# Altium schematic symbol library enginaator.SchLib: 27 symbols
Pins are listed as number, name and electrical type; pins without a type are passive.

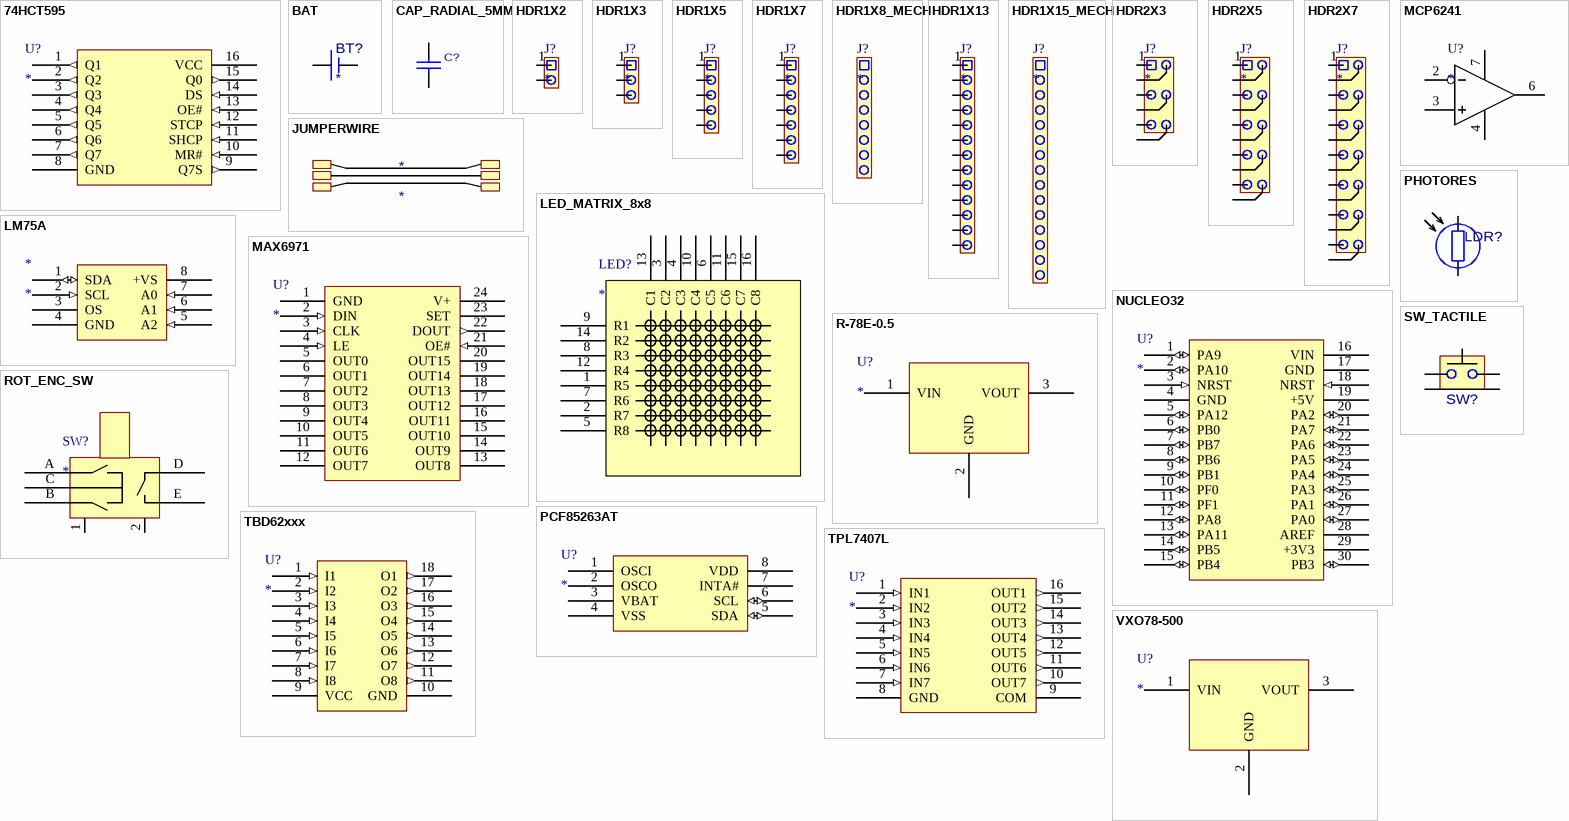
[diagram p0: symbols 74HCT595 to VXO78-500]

## 74HCT595
designator U?
pins: 1 Q1 (out), 2 Q2 (out), 3 Q3 (out), 4 Q4 (out), 5 Q5 (out), 6 Q6 (out), 7 Q7 (out), 8 GND (power), 9 Q7S (out), 10 MR# (in), 11 SHCP (in), 12 STCP (in), 13 OE# (in), 14 DS (in), 15 Q0 (out), 16 VCC (power)

## BAT
designator BT?
pins: 1 +, 2 -

## CAP_RADIAL_5MM
designator C?
pins: 1, 2

## HDR1X2
designator J?
pins: 1, 2

## HDR1X3
designator J?
pins: 1, 2, 3

## HDR1X5
designator J?
pins: 1, 2, 3, 4, 5

## HDR1X7
designator J?
pins: 1, 2, 3, 4, 5, 6, 7

## HDR1X8_MECH
designator J?  (mechanical)

## HDR1X13
designator J?
pins: 1, 2, 3, 4, 5, 6, 7, 8, 9, 10, 11, 12, 13

## HDR1X15_MECH
designator J?  (mechanical)

## HDR2X3
designator J?
pins: 1, 2, 3, 4, 5, 6

## HDR2X5
designator J?
pins: 1, 2, 3, 4, 5, 6, 7, 8, 9, 10

## HDR2X7
designator J?
pins: 1, 2, 3, 4, 5, 6, 7, 8, 9, 10, 11, 12, 13, 14

## JUMPERWIRE
designator *  (mechanical)

## LED_MATRIX_8x8
designator LED?
pins: 1 R5, 2 R7, 3 C2, 4 C3, 5 R8, 6 C5, 7 R6, 8 R3, 9 R1, 10 C4, 11 C6, 12 R4, 13 C1, 14 R2, 15 C7, 16 C8

## LM75A
designator *
pins: 1 SDA (io), 2 SCL (in), 3 OS (oc), 4 GND (power), 5 A2 (in), 6 A1 (in), 7 A0 (in), 8 +VS (power)

## MAX6971
designator U?
pins: 1 GND (power), 2 DIN (in), 3 CLK (in), 4 LE (in), 5 OUT0 (oc), 6 OUT1 (oc), 7 OUT2 (oc), 8 OUT3 (oc), 9 OUT4 (oc), 10 OUT5 (oc), 11 OUT6 (oc), 12 OUT7 (oc), 13 OUT8 (oc), 14 OUT9 (oc), 15 OUT10 (oc), 16 OUT11 (oc), 17 OUT12 (oc), 18 OUT13 (oc), 19 OUT14 (oc), 20 OUT15 (oc), 21 OE# (in), 22 DOUT (out), 23 SET, 24 V+ (power)

## MCP6241
designator U?
pins: 2 VIN-, 3 VIN+, 4 VSS, 6 VOUT, 7 VDD

## NUCLEO32
designator U?
pins: 1 PA9 (io), 2 PA10 (io), 3 NRST (in), 4 GND (power), 5 PA12 (io), 6 PB0 (io), 7 PB7 (io), 8 PB6 (io), 9 PB1 (io), 10 PF0 (io), 11 PF1 (io), 12 PA8 (io), 13 PA11 (io), 14 PB5 (io), 15 PB4 (io), 16 VIN (power), 17 GND (power), 18 NRST (in), 19 +5V (power), 20 PA2 (io), 21 PA7 (io), 22 PA6 (io), 23 PA5 (io), 24 PA4 (io), 25 PA3 (io), 26 PA1 (io), 27 PA0 (io), 28 AREF (power), 29 +3V3 (power), 30 PB3 (io)

## PCF85263AT
designator U?
pins: 1 OSCI, 2 OSCO, 3 VBAT (power), 4 VSS (power), 5 SDA (io), 6 SCL (io), 7 INTA# (oc), 8 VDD (power)

## PHOTORES
designator LDR?
pins: 1, 2

## R-78E-0.5
designator U?
pins: 1 VIN (power), 2 GND (power), 3 VOUT (power)

## ROT_ENC_SW
designator SW?
pins: 1, 2, A, B, C, D, E

## SW_TACTILE
designator SW?, comment EVQ-PF106K  (value not drawn)
Manufacturer: Panasonic Electronic Components
pins: 1 2, 2 4, A 1, B 3

## TBD62xxx
designator U?
pins: 1 I1 (in), 2 I2 (in), 3 I3 (in), 4 I4 (in), 5 I5 (in), 6 I6 (in), 7 I7 (in), 8 I8 (in), 9 VCC (power), 10 GND (power), 11 O8 (out), 12 O7 (out), 13 O6 (out), 14 O5 (out), 15 O4 (out), 16 O3 (out), 17 O2 (out), 18 O1 (out)

## TPL7407L
designator U?
pins: 1 IN1 (in), 2 IN2 (in), 3 IN3 (in), 4 IN4 (in), 5 IN5 (in), 6 IN6 (in), 7 IN7 (in), 8 GND (power), 9 COM (power), 10 OUT7 (out), 11 OUT6 (out), 12 OUT5 (out), 13 OUT4 (out), 14 OUT3 (out), 15 OUT2 (out), 16 OUT1 (out)

## VXO78-500
designator U?
pins: 1 VIN (power), 2 GND (power), 3 VOUT (power)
